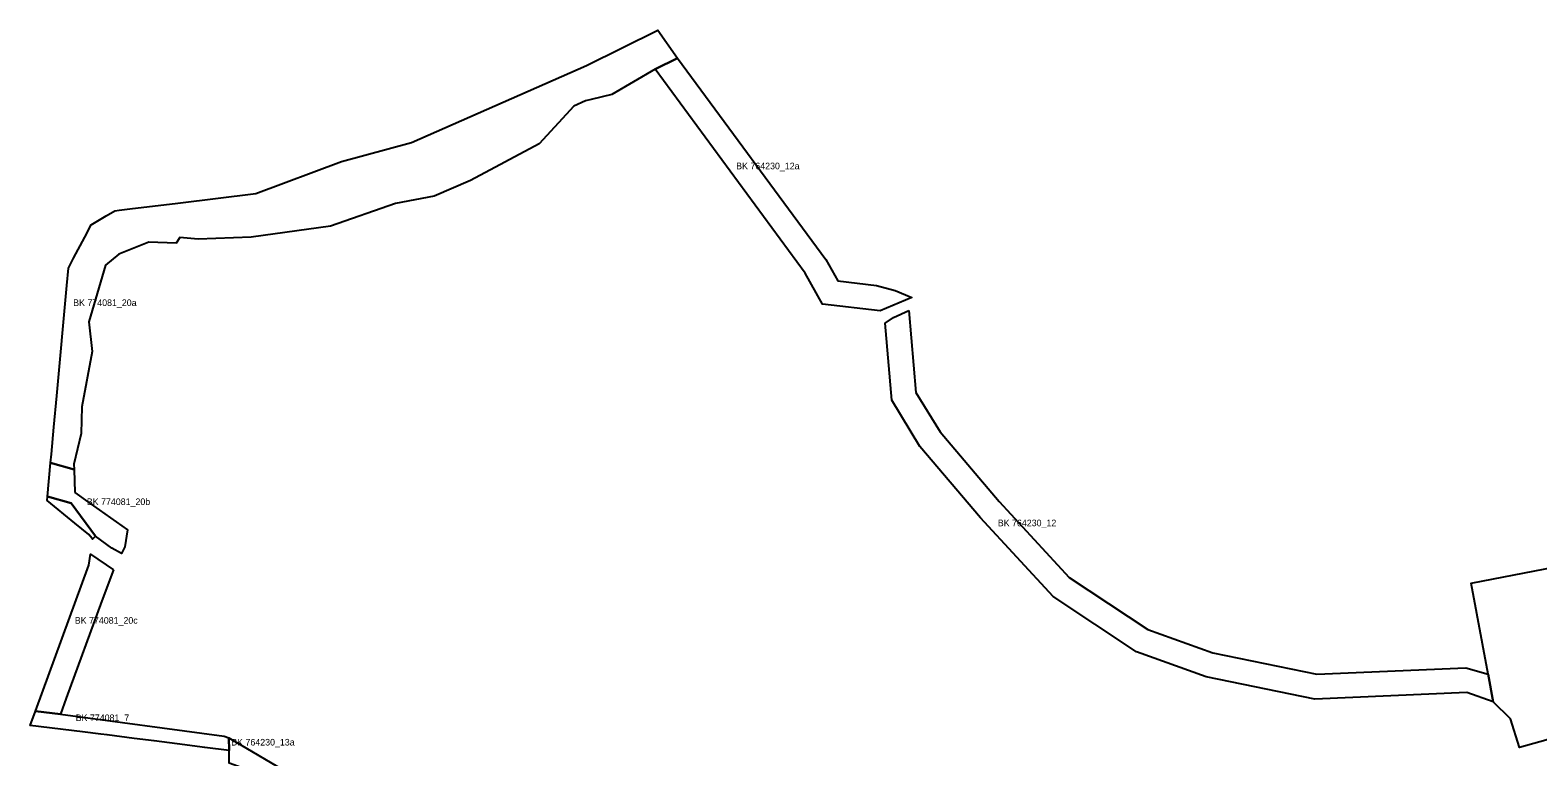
# Model space of a CAD drawing. Extents: x -521616 to -516782, y -1190061 to -1184927.
# Drawn here: x -520810 to -519897, y -1186617 to -1186178 of the extents above; entities that cross this region are included whole.
import ezdxf

# ---------------------------------------------------------------- set-up
doc = ezdxf.new("R2010")
doc.units = 0
for name, color, linetype in [('LBC_s', 7, 'Continuous'), ('LBK_n', 7, 'Continuous'), ('LBK_s', 7, 'Continuous')]:
    doc.layers.add(name, color=color, linetype=linetype)

msp = doc.modelspace()

# ---------------------------------------------------------------- linework, layer by layer
at = {"layer": 'LBC_s'}
msp.add_lwpolyline([(-519870.02, -1186601.09), (-519908.31, -1186611.82), (-519913.72, -1186594.46), (-519924.14, -1186584.14), (-519927.25, -1186567.45), (-519937.54, -1186512.24), (-519873.88, -1186500.08)], dxfattribs=at)
at = {"layer": 'LBK_n'}
for points in [[(-520417.71, -1186194.53), (-520328.05, -1186316.54), (-520320.71, -1186329.41), (-520297.31, -1186332.25), (-520286.04, -1186335.24), (-520275.92, -1186339.39), (-520295.1, -1186347.62), (-520330.01, -1186343.4), (-520340.65, -1186324.73), (-520431.4, -1186201.25)], [(-520759.21, -1186504.19), (-520766.13, -1186523.1), (-520787.69, -1186581.95), (-520791.27, -1186591.71), (-520806.35, -1186589.8), (-520774.1, -1186501.38), (-520773.12, -1186494.88)], [(-520689.18, -1186613.67), (-520703.76, -1186611.79), (-520720.68, -1186609.6), (-520734.44, -1186607.83), (-520746.56, -1186606.26), (-520763.04, -1186604.14), (-520766.82, -1186603.65), (-520777.89, -1186602.33), (-520809.55, -1186598.56), (-520806.35, -1186589.8), (-520791.27, -1186591.71), (-520692.19, -1186604.99), (-520689.28, -1186605.97)], [(-520689.28, -1186605.97), (-520649.52, -1186629.25), (-520645.06, -1186631.17), (-520645.95, -1186633.79), (-520646.07, -1186634.15), (-520647.1, -1186637.19), (-520652.23, -1186652.29), (-520652.69, -1186653.64), (-520654.76, -1186665.44), (-520673.46, -1186654.64), (-520688.88, -1186654.64), (-520688.91, -1186650.76), (-520688.94, -1186646.62), (-520688.97, -1186642.4), (-520688.98, -1186640.76), (-520688.99, -1186638.57), (-520670.45, -1186643.73), (-520665.66, -1186629.65), (-520689.13, -1186621.21), (-520689.15, -1186617.42), (-520689.18, -1186613.67)]]:
    msp.add_lwpolyline(points, close=True, dxfattribs=at)
for points in [[(-520770.01, -1186483.81), (-520784.72, -1186463.92), (-520799.06, -1186459.85), (-520797.21, -1186439.59), (-520782.97, -1186443.63)], [(-520782.97, -1186443.63), (-520782.52, -1186457.51)], [(-520782.52, -1186457.51), (-520774.71, -1186463.15), (-520750.65, -1186480.12), (-520752.19, -1186490.28), (-520754.28, -1186494.42), (-520760.12, -1186491.15), (-520770.01, -1186483.81)]]:
    msp.add_lwpolyline(points, dxfattribs=at)
at = {"layer": 'LBK_s'}
for points in [[(-520673, -1186276.47), (-520621.17, -1186257.07), (-520578.78, -1186245.73), (-520472.97, -1186199.04), (-520429.75, -1186177.66), (-520417.71, -1186194.53), (-520431.4, -1186201.25), (-520457.49, -1186216.54), (-520470.01, -1186219.59), (-520473.52, -1186220.45), (-520480.6, -1186223.62), (-520501.47, -1186246.54), (-520543.03, -1186268.72), (-520565.02, -1186278.04), (-520588.51, -1186282.51), (-520627.83, -1186296.3), (-520675.73, -1186303.01), (-520707.97, -1186304.13), (-520718.97, -1186303.2), (-520721.2, -1186306.55), (-520737.79, -1186305.99), (-520755.87, -1186313.26), (-520763.88, -1186319.97), (-520773.95, -1186354.08), (-520772.08, -1186372.16), (-520778.23, -1186405.7), (-520778.6, -1186421.73), (-520783.08, -1186440.37), (-520782.97, -1186443.63), (-520797.21, -1186439.59), (-520796.72, -1186434.3), (-520795.23, -1186418.02), (-520793.49, -1186398.99), (-520787.38, -1186332.28), (-520786.41, -1186321.7), (-520783.24, -1186315.71), (-520776.5, -1186302.96), (-520772.54, -1186295.47), (-520763.58, -1186290.1), (-520758.36, -1186286.97), (-520755.78, -1186286.65), (-520749.24, -1186285.85), (-520720.25, -1186282.28)], [(-520277.83, -1186347.36), (-520273.53, -1186396.85), (-520258.92, -1186420.73), (-520223.12, -1186462.9), (-520180.75, -1186508.83), (-520133.23, -1186540.41), (-520093.88, -1186554.45), (-520030.86, -1186567.44), (-519940.82, -1186563.54), (-519927.25, -1186567.45), (-519924.14, -1186584.14), (-519940.17, -1186578.53), (-520032.07, -1186582.51), (-520097.93, -1186568.93), (-520140, -1186553.92), (-520190.55, -1186520.32), (-520234.35, -1186472.84), (-520271.11, -1186429.55), (-520288.17, -1186401.67), (-520292.22, -1186355.01), (-520287.15, -1186351.46)], [(-520799.06, -1186459.85), (-520784.72, -1186463.92), (-520770.01, -1186483.81), (-520771.73, -1186485.73), (-520772.25, -1186485.09), (-520774.04, -1186482.84), (-520782.48, -1186475.98), (-520799.29, -1186462.32)]]:
    msp.add_lwpolyline(points, close=True, dxfattribs=at)

# ---------------------------------------------------------------- texts
at = {"layer": 'LBK_n'}
for s, p in [('BK 764230_12a', (-520382.31, -1186261.85)), ('BK 774081_20b', (-520775.27, -1186465.06)), ('BK 774081_20c', (-520782.54, -1186536.87)), ('BK 774081_7', (-520782.01, -1186595.81)), ('BK 764230_13a', (-520687.86, -1186610.58))]:
    msp.add_text(s, height=4, dxfattribs=at).set_placement(p)
at = {"layer": 'LBK_s'}
for s, p in [('BK 774081_20a', (-520783.52, -1186344.6)), ('BK 764230_12', (-520223.98, -1186477.89))]:
    msp.add_text(s, height=4, dxfattribs=at).set_placement(p)

doc.saveas('drawing.dxf')
